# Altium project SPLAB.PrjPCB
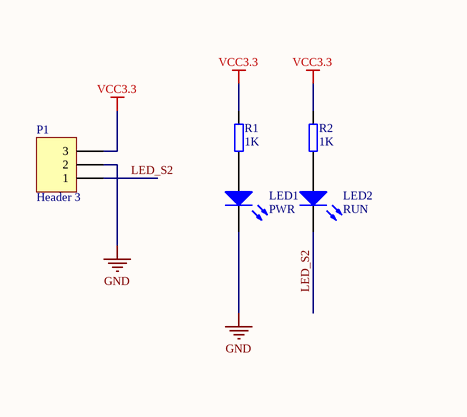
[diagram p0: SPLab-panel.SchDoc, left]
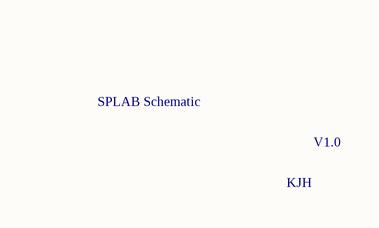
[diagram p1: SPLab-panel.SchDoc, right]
1 sheet, 5 parts. Net scope: global (net labels, ports and power ports of the same name join across sheets).
Board file: SPLab-panel.PcbDoc

## Sheet SPLab-panel.SchDoc
size B; SheetNumber: 0; SheetTotal: 0

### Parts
LED1  PWR  [LED]
LED2  RUN  [LED]
P1  Header 3  [HDR1X3]
R1  1K  [SM0603]
R2  1K  [SM0603]

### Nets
GND: LED1.2(K) P1.2
VCC3.3: P1.3 R1.2 R2.2
LED_S2: LED2.2(K) P1.1
NetLED1_1: LED1.1(A) R1.1
NetLED2_1: LED2.1(A) R2.1

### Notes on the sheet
- SPLAB Schematic
- KJH
- V1.0

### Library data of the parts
LED1 LED2 = LED0: Typical INFRARED GaAs LED
P1 = Header 3: Header, 3-Pin
R1 R2 = R: 电阻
